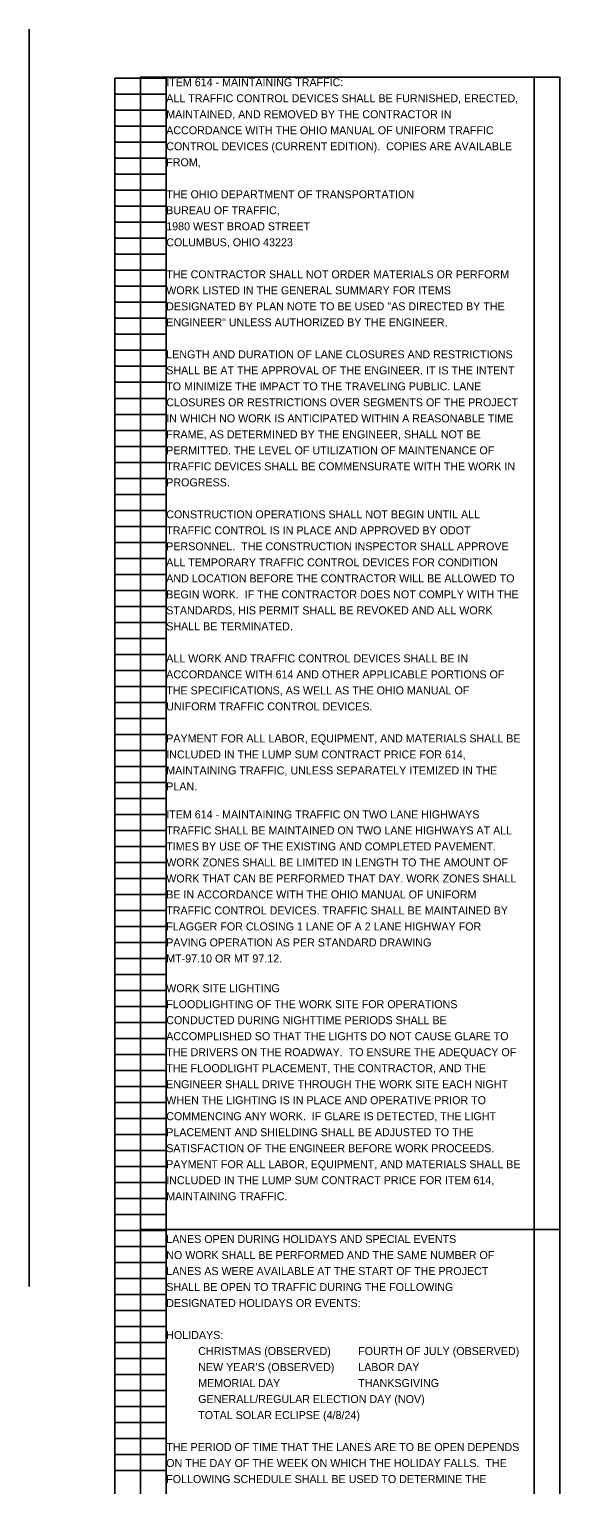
# Model space of a CAD drawing. Extents: x 0 to 19, y -301 to 22.
# Drawn here: x 0 to 9.29, y -3.47 to 22 of the extents above; entities that cross this region are included whole.
import ezdxf

# ---------------------------------------------------------------- set-up
doc = ezdxf.new("R2010")
doc.units = 0
doc.layers.add('SC_Scratch1', color=7, linetype='Continuous')
doc.layers.add('SH_Text', color=7, linetype='Continuous')

msp = doc.modelspace()

# ---------------------------------------------------------------- linework, layer by layer
at = {"layer": 'SC_Scratch1'}
for p, q in [((0, 22), (0, 0)), ((1.5, 21.14), (2.4, 21.14)), ((1.5, 0.98), (1.5, 21.14)), ((2.4, 0.98), (2.4, 21.14)), ((8.84, 0.98), (8.84, 21.14)), ((1.5, 20.86), (2.4, 20.86)), ((1.5, 20.58), (2.4, 20.58)), ((1.5, 20.3), (2.4, 20.3)), ((1.5, 20.02), (2.4, 20.02)), ((1.5, 19.74), (2.4, 19.74)), ((1.5, 19.46), (2.4, 19.46)), ((1.5, 19.18), (2.4, 19.18)), ((1.5, 18.9), (2.4, 18.9)), ((1.5, 18.62), (2.4, 18.62)), ((1.5, 18.34), (2.4, 18.34)), ((1.5, 18.06), (2.4, 18.06)), ((1.5, 17.78), (2.4, 17.78)), ((1.5, 17.5), (2.4, 17.5)), ((1.5, 17.22), (2.4, 17.22)), ((1.5, 16.94), (2.4, 16.94)), ((1.5, 16.66), (2.4, 16.66)), ((1.5, 16.38), (2.4, 16.38)), ((1.5, 16.1), (2.4, 16.1)), ((1.5, 15.82), (2.4, 15.82)), ((1.5, 15.54), (2.4, 15.54)), ((1.5, 15.26), (2.4, 15.26)), ((1.5, 14.98), (2.4, 14.98)), ((1.5, 14.7), (2.4, 14.7)), ((1.5, 14.42), (2.4, 14.42)), ((1.5, 14.14), (2.4, 14.14)), ((1.5, 13.86), (2.4, 13.86)), ((1.5, 13.58), (2.4, 13.58)), ((1.5, 13.3), (2.4, 13.3)), ((1.5, 13.02), (2.4, 13.02)), ((1.5, 12.74), (2.4, 12.74)), ((1.5, 12.46), (2.4, 12.46)), ((1.5, 12.18), (2.4, 12.18)), ((1.5, 11.9), (2.4, 11.9)), ((1.5, 11.62), (2.4, 11.62)), ((1.5, 11.34), (2.4, 11.34)), ((1.5, 11.06), (2.4, 11.06)), ((1.5, 10.78), (2.4, 10.78)), ((1.5, 10.5), (2.4, 10.5)), ((1.5, 10.22), (2.4, 10.22)), ((1.5, 9.94), (2.4, 9.94)), ((1.5, 9.66), (2.4, 9.66)), ((1.5, 9.38), (2.4, 9.38)), ((1.5, 9.1), (2.4, 9.1)), ((1.5, 8.82), (2.4, 8.82)), ((1.5, 8.54), (2.4, 8.54)), ((1.5, 8.26), (2.4, 8.26)), ((1.5, 7.98), (2.4, 7.98)), ((1.5, 7.7), (2.4, 7.7)), ((1.5, 7.42), (2.4, 7.42)), ((1.5, 7.14), (2.4, 7.14)), ((1.5, 6.86), (2.4, 6.86)), ((1.5, 6.58), (2.4, 6.58)), ((1.5, 6.3), (2.4, 6.3)), ((1.5, 6.02), (2.4, 6.02)), ((1.5, 5.74), (2.4, 5.74)), ((1.5, 5.46), (2.4, 5.46)), ((1.5, 5.18), (2.4, 5.18)), ((1.5, 4.9), (2.4, 4.9)), ((1.5, 4.62), (2.4, 4.62)), ((1.5, 4.34), (2.4, 4.34)), ((1.5, 4.06), (2.4, 4.06)), ((1.5, 3.78), (2.4, 3.78)), ((1.5, 3.5), (2.4, 3.5)), ((1.5, 3.22), (2.4, 3.22)), ((1.5, 2.94), (2.4, 2.94)), ((1.5, 2.66), (2.4, 2.66)), ((1.5, 2.38), (2.4, 2.38)), ((1.5, 2.1), (2.4, 2.1)), ((1.5, 1.82), (2.4, 1.82)), ((1.5, 1.54), (2.4, 1.54)), ((1.5, 1.26), (2.4, 1.26)), ((1.5, 0.98), (2.4, 0.98)), ((1.5, 0.98), (2.4, 0.98)), ((1.5, -19.18), (1.5, 0.98)), ((2.4, -19.18), (2.4, 0.98)), ((8.84, -19.18), (8.84, 0.98)), ((1.5, 0.7), (2.4, 0.7)), ((1.5, 0.42), (2.4, 0.42)), ((1.5, 0.14), (2.4, 0.14)), ((1.5, -0.14), (2.4, -0.14)), ((1.5, -0.42), (2.4, -0.42)), ((1.5, -0.7), (2.4, -0.7)), ((1.5, -0.98), (2.4, -0.98)), ((1.5, -1.26), (2.4, -1.26)), ((1.5, -1.54), (2.4, -1.54)), ((1.5, -1.82), (2.4, -1.82)), ((1.5, -2.1), (2.4, -2.1)), ((1.5, -2.38), (2.4, -2.38)), ((1.5, -2.66), (2.4, -2.66)), ((1.5, -2.94), (2.4, -2.94)), ((1.5, -3.22), (2.4, -3.22))]:
    msp.add_line(p, q, dxfattribs=at)
for points in [[(1.95, 21.157), (9.29, 21.157), (9.29, 0.997), (1.95, 0.997)], [(1.95, 0.997), (9.29, 0.997), (9.29, -19.163), (1.95, -19.163)]]:
    msp.add_lwpolyline(points, close=True, dxfattribs=at)

# ---------------------------------------------------------------- texts
at = {"layer": 'SH_Text'}
for s, p in [('ITEM 614 - MAINTAINING TRAFFIC:', (2.4, 21)), ('ALL TRAFFIC CONTROL DEVICES SHALL BE FURNISHED, ERECTED, ', (2.4, 20.72)), ('MAINTAINED, AND REMOVED BY THE CONTRACTOR IN ', (2.4, 20.44)), ('ACCORDANCE WITH THE OHIO MANUAL OF UNIFORM TRAFFIC ', (2.4, 20.16)), ('CONTROL DEVICES (CURRENT EDITION).  COPIES ARE AVAILABLE ', (2.4, 19.88)), ('FROM,', (2.4, 19.6)), ('THE OHIO DEPARTMENT OF TRANSPORTATION', (2.4, 19.04)), ('BUREAU OF TRAFFIC,', (2.4, 18.76)), ('1980 WEST BROAD STREET', (2.4, 18.48)), ('COLUMBUS, OHIO 43223', (2.4, 18.2)), ('THE CONTRACTOR SHALL NOT ORDER MATERIALS OR PERFORM ', (2.4, 17.64)), ('WORK LISTED IN THE GENERAL SUMMARY FOR ITEMS ', (2.4, 17.36)), ('DESIGNATED BY PLAN NOTE TO BE USED "AS DIRECTED BY THE ', (2.4, 17.08)), ('ENGINEER" UNLESS AUTHORIZED BY THE ENGINEER.', (2.4, 16.8)), ('LENGTH AND DURATION OF LANE CLOSURES AND RESTRICTIONS ', (2.4, 16.24)), ('SHALL BE AT THE APPROVAL OF THE ENGINEER. IT IS THE INTENT ', (2.4, 15.96)), ('TO MINIMIZE THE IMPACT TO THE TRAVELING PUBLIC. LANE ', (2.4, 15.68)), ('CLOSURES OR RESTRICTIONS OVER SEGMENTS OF THE PROJECT ', (2.4, 15.4)), ('IN WHICH NO WORK IS ANTICIPATED WITHIN A REASONABLE TIME ', (2.4, 15.12)), ('FRAME, AS DETERMINED BY THE ENGINEER, SHALL NOT BE ', (2.4, 14.84)), ('PERMITTED. THE LEVEL OF UTILIZATION OF MAINTENANCE OF ', (2.4, 14.56)), ('TRAFFIC DEVICES SHALL BE COMMENSURATE WITH THE WORK IN ', (2.4, 14.28)), ('PROGRESS.', (2.4, 14)), ('CONSTRUCTION OPERATIONS SHALL NOT BEGIN UNTIL ALL ', (2.4, 13.44)), ('TRAFFIC CONTROL IS IN PLACE AND APPROVED BY ODOT ', (2.4, 13.16)), ('PERSONNEL.  THE CONSTRUCTION INSPECTOR SHALL APPROVE ', (2.4, 12.88)), ('ALL TEMPORARY TRAFFIC CONTROL DEVICES FOR CONDITION ', (2.4, 12.6)), ('AND LOCATION BEFORE THE CONTRACTOR WILL BE ALLOWED TO ', (2.4, 12.32)), ('BEGIN WORK.  IF THE CONTRACTOR DOES NOT COMPLY WITH THE ', (2.4, 12.04)), ('STANDARDS, HIS PERMIT SHALL BE REVOKED AND ALL WORK ', (2.4, 11.76)), ('SHALL BE TERMINATED.', (2.4, 11.48)), ('ALL WORK AND TRAFFIC CONTROL DEVICES SHALL BE IN ', (2.4, 10.92)), ('ACCORDANCE WITH 614 AND OTHER APPLICABLE PORTIONS OF ', (2.4, 10.64)), ('THE SPECIFICATIONS, AS WELL AS THE OHIO MANUAL OF ', (2.4, 10.36)), ('UNIFORM TRAFFIC CONTROL DEVICES.  ', (2.4, 10.08)), ('PAYMENT FOR ALL LABOR, EQUIPMENT, AND MATERIALS SHALL BE ', (2.4, 9.52)), ('INCLUDED IN THE LUMP SUM CONTRACT PRICE FOR 614, ', (2.4, 9.24)), ('MAINTAINING TRAFFIC, UNLESS SEPARATELY ITEMIZED IN THE ', (2.4, 8.96)), ('PLAN.', (2.4, 8.68)), ('ITEM 614 - MAINTAINING TRAFFIC ON TWO LANE HIGHWAYS', (2.4, 8.19)), ('TRAFFIC SHALL BE MAINTAINED ON TWO LANE HIGHWAYS AT ALL ', (2.4, 7.91)), ('TIMES BY USE OF THE EXISTING AND COMPLETED PAVEMENT.  ', (2.4, 7.63)), ('WORK ZONES SHALL BE LIMITED IN LENGTH TO THE AMOUNT OF ', (2.4, 7.35)), ('WORK THAT CAN BE PERFORMED THAT DAY. WORK ZONES SHALL ', (2.4, 7.07)), ('BE IN ACCORDANCE WITH THE OHIO MANUAL OF UNIFORM ', (2.4, 6.79)), ('TRAFFIC CONTROL DEVICES. TRAFFIC SHALL BE MAINTAINED BY ', (2.4, 6.51)), ('FLAGGER FOR CLOSING 1 LANE OF A 2 LANE HIGHWAY FOR ', (2.4, 6.23)), ('PAVING OPERATION AS PER STANDARD DRAWING', (2.4, 5.95)), ('MT-97.10 OR MT 97.12.', (2.4, 5.67)), ('WORK SITE LIGHTING', (2.4, 5.15)), ('FLOODLIGHTING OF THE WORK SITE FOR OPERATIONS ', (2.4, 4.87)), ('CONDUCTED DURING NIGHTTIME PERIODS SHALL BE ', (2.4, 4.59)), ('ACCOMPLISHED SO THAT THE LIGHTS DO NOT CAUSE GLARE TO ', (2.4, 4.31)), ('THE DRIVERS ON THE ROADWAY.  TO ENSURE THE ADEQUACY OF ', (2.4, 4.03)), ('THE FLOODLIGHT PLACEMENT, THE CONTRACTOR, AND THE ', (2.4, 3.75)), ('ENGINEER SHALL DRIVE THROUGH THE WORK SITE EACH NIGHT ', (2.4, 3.47)), ('WHEN THE LIGHTING IS IN PLACE AND OPERATIVE PRIOR TO ', (2.4, 3.19)), ('COMMENCING ANY WORK.  IF GLARE IS DETECTED, THE LIGHT ', (2.4, 2.91)), ('PLACEMENT AND SHIELDING SHALL BE ADJUSTED TO THE ', (2.4, 2.63)), ('SATISFACTION OF THE ENGINEER BEFORE WORK PROCEEDS.  ', (2.4, 2.35)), ('PAYMENT FOR ALL LABOR, EQUIPMENT, AND MATERIALS SHALL BE ', (2.4, 2.07)), ('INCLUDED IN THE LUMP SUM CONTRACT PRICE FOR ITEM 614, ', (2.4, 1.79)), ('MAINTAINING TRAFFIC.', (2.4, 1.51)), ('LANES OPEN DURING HOLIDAYS AND SPECIAL EVENTS', (2.4, 0.761)), ('NO WORK SHALL BE PERFORMED AND THE SAME NUMBER OF ', (2.4, 0.481)), ('LANES AS WERE AVAILABLE AT THE START OF THE PROJECT ', (2.4, 0.201)), ('SHALL BE OPEN TO TRAFFIC DURING THE FOLLOWING ', (2.4, -0.079)), ('DESIGNATED HOLIDAYS OR EVENTS:', (2.4, -0.359)), ('HOLIDAYS:', (2.4, -0.919)), ('CHRISTMAS (OBSERVED)', (2.96, -1.199)), ('FOURTH OF JULY (OBSERVED)', (5.76, -1.199)), ('NEW YEAR’S (OBSERVED)', (2.96, -1.479)), ('LABOR DAY', (5.76, -1.479)), ('MEMORIAL DAY          ', (2.96, -1.759)), ('THANKSGIVING', (5.76, -1.759)), ('GENERALL/REGULAR ELECTION DAY (NOV)', (2.96, -2.039)), ('TOTAL SOLAR ECLIPSE (4/8/24) ', (2.96, -2.319)), ('THE PERIOD OF TIME THAT THE LANES ARE TO BE OPEN DEPENDS ', (2.4, -2.879)), ('ON THE DAY OF THE WEEK ON WHICH THE HOLIDAY FALLS.  THE ', (2.4, -3.159)), ('FOLLOWING SCHEDULE SHALL BE USED TO DETERMINE THE ', (2.4, -3.439))]:
    msp.add_text(s, height=0.14, dxfattribs=at).set_placement(p)

doc.saveas('drawing.dxf')
